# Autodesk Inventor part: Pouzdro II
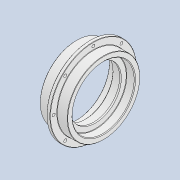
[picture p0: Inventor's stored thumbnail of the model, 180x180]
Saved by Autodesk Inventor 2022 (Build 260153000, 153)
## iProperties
Created: 2025-05
Part Number: Pouzdro II
Material: Všeobecné
Document SubType Name: Modeling
Designer: jbart
Density: 1 g/cm^3
Appearance: Hladká – bílá
Mass: 7788.21 g
Surface Area: 6273.05 cm^2
Volume: 7788.21 cm^3
Author: jbart
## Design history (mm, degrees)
sketch "Náčrt1"
  geometry: L1 (0, 0)-(110, 0); L2 (0, 160)-(52, 160); L3 (52, 160)-(52, 150); L4 (52, 150)-(62, 150); L5 (62, 150)-(62, 180); L6 (62, 180)-(110, 180); L7 (110, 180)-(110, 190); L8 (110, 190)-(110, 190); L9 (110, 190)-(110, 210); L10 (110, 210)-(50, 210); L11 (50, 210)-(50, 250); L12 (50, 250)-(30, 250); L13 (30, 250)-(30, 210); L14 (30, 210)-(0, 210); L15 (0, 190)-(0, 160); L16 (0, 210)-(-49, 210); L17 (-49, 210)-(-49, 190); L18 (-49, 190)-(0, 190); 2 further points
  constraints: 36 end point, 14 perpendicular, 3 horizontal, 3 point on line, 2 vertical alignment, 1 midpoint
  dimensions: "d0" = 110 distance of L1.start L1.end; "d1" = 320 diameter of L2 L1; "d2" = 360 diameter of L6 L1; "d3" = 380 diameter of L8 L1; "d4" = 52 distance of L2.start L2.end; "d5" = 48 distance of L5.end L6.end; "d6" = 10 distance of L3.end L4.end; "d7" = 20 distance of L11.end L12.end; "d8" = 30 distance of L13.end L14.end; "d9" = 300 diameter of L4 L1; "d14" = 420 diameter of L14 L1; "d15" = 500 diameter of L12 L1; "d18" = 49 distance of L14.end L16.end; "d19" = 20 distance of L16.end L17.end; "d20" = 30 distance from line of L1.start L13; "d37" = 49 distance from line of L17 L1.start (derived)
revolve "Rotace1" sketch "Náčrt1" stored, may be unused: angle "d10" = 90 deg
chamfer "Zkosení1" distance "d11" = 4; stored, may be unused: second distance "d12" = 2, angle "d13" = 45 deg
sketch "Náčrt2" dims "d16" = 460
  geometry: L1 (0, 0)-(0, 230); 2 further points
  constraints: 2 coincident, 2 end point, 1 vertical, 1 vertical alignment, 2 other
hole "Díra1" sketch "Náčrt2" at (0, 230) diameter "d21" = 17.5; stored, may be unused: countersink angle "d25" = 90 deg, drill point angle "d27" = 118 deg; dims "d22" = 6, "d23" = 20, "d24" = 12, "d26" = 8
pattern_circular "Kruhové pole1" dims angle "d29" = 360 deg
chamfer "Zkosení2" distance "d31" = 2; stored, may be unused: second distance "d32" = 2, angle "d33" = 45 deg
fillet "Zaoblení1" dims "d34" = 2
fillet "Zaoblení2" dims "d35" = 2
fillet "Zaoblení3" dims "d38" = 2
node "Těleso1"
